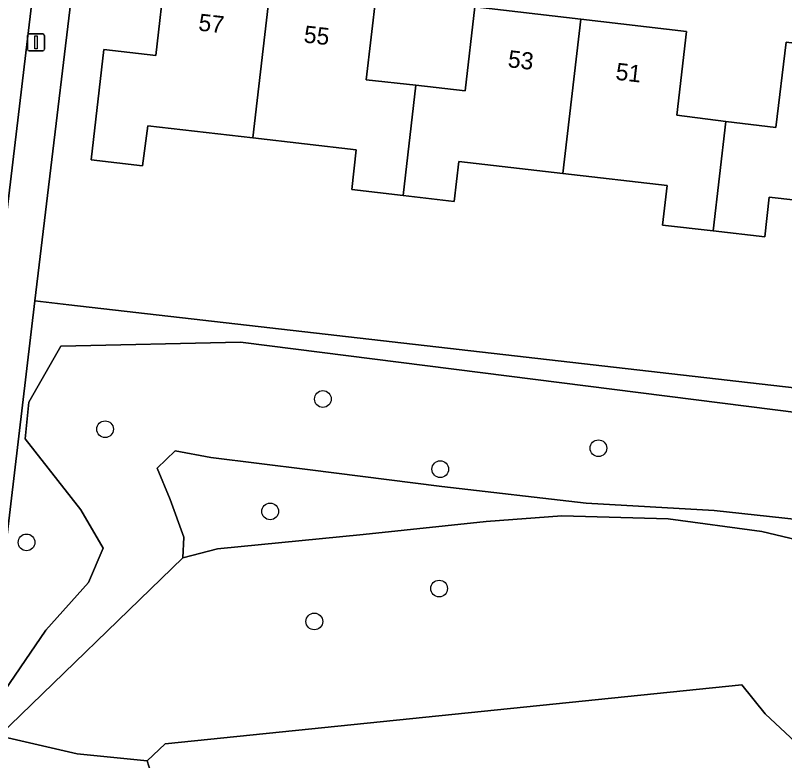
# Model space of a CAD drawing. Extents: x 161241 to 161758, y 384138 to 384885.
# Drawn here: x 161385.2 to 161430.25, y 384299.26 to 384342.9 of the extents above; entities that cross this region are included whole.
import ezdxf

# ---------------------------------------------------------------- set-up
doc = ezdxf.new("R2010")
doc.units = 0
for name, color, linetype in [('IMGEO_Boom', 7, 'Continuous'), ('IMGEO_Erf', 7, 'Continuous'), ('IMGEO_Groenvoorziening', 7, 'Continuous'), ('IMGEO_Lichtmast', 7, 'Continuous'), ('IMGEO_Meer_plas_ven_vijver', 7, 'Continuous'), ('IMGEO_Pand', 7, 'Continuous'), ('IMGEO_Pand_nummerreeks', 7, 'Continuous'), ('IMGEO_Rijbaan_lokaal_open', 7, 'Continuous'), ('IMGEO_Voetpad_open', 7, 'Continuous')]:
    doc.layers.add(name, color=color, linetype=linetype)

msp = doc.modelspace()

# ---------------------------------------------------------------- linework, layer by layer
at = {"layer": 'IMGEO_Boom'}
for centre in [(161403.207, 384320.433), (161390.453, 384318.663), (161419.341, 384317.551), (161410.083, 384316.325), (161400.121, 384313.852), (161385.855, 384312.039), (161410.015, 384309.336), (161402.707, 384307.407)]:
    msp.add_circle(centre, 0.489, dxfattribs=at)
at = {"layer": 'IMGEO_Erf'}
for points in [[(161389.324, 384351.032), (161386.343, 384326.184), (161388.33, 384325.957), (161461.508, 384317.582)], [(161435.407, 384331.567), (161429.348, 384332.261), (161429.08, 384329.926), (161426.059, 384330.272), (161423.099, 384330.611), (161423.366, 384332.945), (161417.254, 384333.645), (161411.165, 384334.342), (161410.897, 384332.007), (161407.906, 384332.349), (161404.896, 384332.694), (161405.163, 384335.028), (161399.102, 384335.722), (161392.952, 384336.426), (161392.653, 384334.095), (161389.643, 384334.439), (161390.383, 384340.906), (161393.423, 384340.557), (161393.992, 384345.524)], [(161406.328, 384344.133), (161405.748, 384339.132), (161408.659, 384338.804), (161411.549, 384338.479), (161412.108, 384343.396), (161418.308, 384342.672), (161424.503, 384341.949), (161423.925, 384337.049), (161426.807, 384336.692), (161429.727, 384336.331), (161430.333, 384341.322), (161436.46, 384340.603), (161442.63, 384339.878), (161442.059, 384334.91), (161444.953, 384334.559), (161447.848, 384334.208), (161448.464, 384339.19), (161454.606, 384338.469), (161460.834, 384337.737), (161460.268, 384332.792), (161463.222, 384332.441), (161463.801, 384337.463), (161464.362, 384342.323), (161438.38, 384345.338)]]:
    msp.add_lwpolyline(points, dxfattribs=at)
at = {"layer": 'IMGEO_Groenvoorziening'}
for points in [[(161383.959, 384302.494), (161386.987, 384306.894), (161389.478, 384309.685), (161390.337, 384311.694), (161389.037, 384313.944), (161385.772, 384318.093), (161385.994, 384320.251), (161387.855, 384323.519), (161398.386, 384323.765), (161459.305, 384316.043), (161461.281, 384315.825), (161461.508, 384317.582), (161388.33, 384325.957), (161386.343, 384326.184), (161383.222, 384299.937)], [(161459.305, 384316.043), (161398.386, 384323.765), (161387.855, 384323.519), (161385.994, 384320.251), (161385.772, 384318.093), (161389.037, 384313.944), (161390.337, 384311.694), (161389.478, 384309.685), (161386.987, 384306.894), (161383.959, 384302.494)], [(161384.224, 384300.714), (161395.011, 384311.131), (161395.059, 384312.349), (161394.273, 384314.553), (161393.513, 384316.374), (161394.564, 384317.399), (161396.649, 384317.013), (161402.312, 384316.298), (161410.179, 384315.316), (161418.62, 384314.329), (161426.121, 384313.903), (161439.251, 384312.48)], [(161439.251, 384312.48), (161426.121, 384313.903), (161418.62, 384314.329), (161410.179, 384315.316), (161402.312, 384316.298), (161396.649, 384317.013), (161394.564, 384317.399), (161393.513, 384316.374), (161394.273, 384314.553), (161395.059, 384312.349), (161395.011, 384311.131), (161397.034, 384311.657), (161405.56, 384312.503), (161412.779, 384313.261), (161417.208, 384313.591), (161423.422, 384313.41), (161428.913, 384312.669), (161432.686, 384311.783)], [(161432.686, 384311.783), (161428.913, 384312.669), (161423.422, 384313.41), (161417.208, 384313.591), (161412.779, 384313.261), (161405.56, 384312.503), (161397.034, 384311.657), (161395.011, 384311.131), (161384.224, 384300.714), (161388.81, 384299.652), (161392.922, 384299.244), (161393.981, 384300.233), (161427.745, 384303.693), (161429.104, 384302.003), (161436.208, 384295.365)], [(161455.857, 384306.708), (161442.591, 384294.989), (161442.679, 384294.556), (161446.465, 384294.246), (161447.299, 384293.465), (161446.512, 384291.967), (161444.942, 384291.369), (161408.228, 384291.268), (161406.059, 384291.702), (161401.921, 384293.983), (161394.316, 384296.874), (161393.316, 384298.001), (161392.922, 384299.244), (161388.81, 384299.652), (161384.224, 384300.714)]]:
    msp.add_lwpolyline(points, dxfattribs=at)
at = {"layer": 'IMGEO_Lichtmast'}
for p, q in [((161385.911, 384340.915), (161385.911, 384341.715)), ((161385.911, 384341.715), (161385.911, 384340.915)), ((161386.011, 384341.815), (161386.801, 384341.815)), ((161386.801, 384341.815), (161386.011, 384341.815)), ((161386.901, 384341.715), (161386.901, 384340.915)), ((161386.901, 384340.915), (161386.901, 384341.715)), ((161386.801, 384340.815), (161386.011, 384340.815)), ((161386.011, 384340.815), (161386.801, 384340.815))]:
    msp.add_line(p, q, dxfattribs=at)
msp.add_lwpolyline([(161386.331, 384341.69), (161386.481, 384341.69), (161386.481, 384340.94), (161386.331, 384340.94), (161386.331, 384341.69)], dxfattribs=at)
for centre, start, end in [((161386.011, 384341.715), 90, 180), ((161386.011, 384341.715), 90, 180), ((161386.801, 384341.715), 0, 90), ((161386.801, 384341.715), 360, 90), ((161386.011, 384340.915), 180, 270), ((161386.011, 384340.915), 180, 270), ((161386.801, 384340.915), 270, 0), ((161386.801, 384340.915), 270, 0)]:
    msp.add_arc(centre, 0.1, start, end, dxfattribs=at)
at = {"layer": 'IMGEO_Meer_plas_ven_vijver'}
msp.add_lwpolyline([(161393.981, 384300.233), (161392.922, 384299.244), (161393.316, 384298.001), (161394.316, 384296.874), (161401.921, 384293.983), (161406.059, 384291.702), (161408.228, 384291.268), (161444.942, 384291.369), (161446.512, 384291.967), (161447.299, 384293.465), (161446.465, 384294.246), (161442.679, 384294.556), (161436.208, 384295.365), (161429.104, 384302.003), (161427.745, 384303.693)], close=True, dxfattribs=at)
at = {"layer": 'IMGEO_Pand'}
for points in [[(161400.164, 384344.828), (161393.992, 384345.524), (161393.423, 384340.557), (161390.383, 384340.906), (161389.643, 384334.439), (161392.653, 384334.095), (161392.952, 384336.426), (161399.102, 384335.722)], [(161408.659, 384338.804), (161405.748, 384339.132), (161406.328, 384344.133), (161400.164, 384344.828), (161399.102, 384335.722), (161405.163, 384335.028), (161404.896, 384332.694), (161407.906, 384332.349)], [(161407.906, 384332.349), (161410.897, 384332.007), (161411.165, 384334.342), (161417.254, 384333.645), (161418.308, 384342.672), (161412.108, 384343.396), (161411.549, 384338.479), (161408.659, 384338.804)], [(161426.807, 384336.692), (161423.925, 384337.049), (161424.503, 384341.949), (161418.308, 384342.672), (161417.254, 384333.645), (161423.366, 384332.945), (161423.099, 384330.611), (161426.059, 384330.272)], [(161436.46, 384340.603), (161430.333, 384341.322), (161429.727, 384336.331), (161426.807, 384336.692), (161426.059, 384330.272), (161429.08, 384329.926), (161429.348, 384332.261), (161435.407, 384331.567)]]:
    msp.add_lwpolyline(points, close=True, dxfattribs=at)
at = {"layer": 'IMGEO_Rijbaan_lokaal_open'}
msp.add_lwpolyline([(161388.102, 384360.026), (161388.45, 384362.95), (161388.474, 384363.189), (161382.385, 384363.904), (161382.338, 384363.509), (161382.029, 384360.807), (161380.816, 384350.22), (161380.553, 384347.92), (161375.412, 384304.063), (161375.385, 384303.831), (161374.158, 384293.356), (161374.069, 384292.593), (161373.523, 384287.939), (161379.384, 384287.252), (161380.279, 384294.53), (161380.712, 384297.896), (161380.767, 384298.362), (161386.821, 384349.251)], close=True, dxfattribs=at)
at = {"layer": 'IMGEO_Voetpad_open'}
msp.add_lwpolyline([(161388.778, 384366.166), (161388.754, 384365.965), (161388.474, 384363.189), (161388.45, 384362.95), (161388.102, 384360.026), (161388.591, 384359.969), (161387.33, 384349.191), (161386.821, 384349.251), (161380.767, 384298.362), (161381.263, 384298.301), (161383.002, 384298.118), (161383.058, 384298.581), (161383.222, 384299.937), (161386.343, 384326.184), (161389.324, 384351.032), (161391.147, 384350.82), (161391.7, 384355.381), (161392.099, 384359.279), (161393.196, 384368.833)], dxfattribs=at)

# ---------------------------------------------------------------- texts
at = {"layer": 'IMGEO_Pand_nummerreeks'}
for s, rotation, p in [('57', 353.5665, (161395.887, 384342.01)), ('55', 353.5665, (161402.055, 384341.314)), ('53', 353.3414, (161414.005, 384339.872)), ('51', 353.3414, (161420.315, 384339.135))]:
    msp.add_text(s, height=1, rotation=rotation, dxfattribs=at).set_placement(p)

doc.saveas('drawing.dxf')
